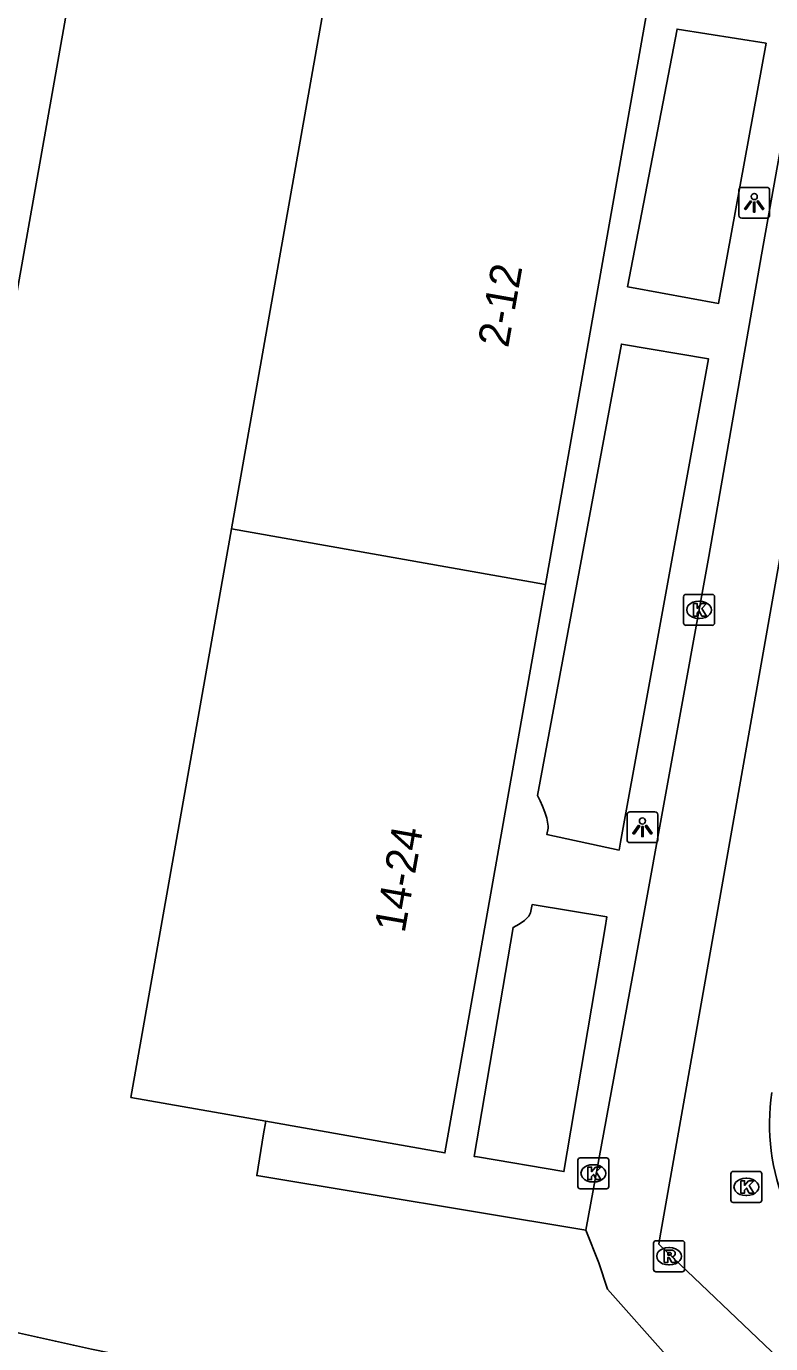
# Model space of a CAD drawing. Extents: x 161402 to 161933, y 381650 to 382313.
# Drawn here: x 161750.87 to 161774.94, y 381882.31 to 381924.89 of the extents above; entities that cross this region are included whole.
import ezdxf

# ---------------------------------------------------------------- set-up
doc = ezdxf.new("R2010")
doc.units = 0
for name, color, linetype in [('IMGEO_Groenvoorziening', 7, 'Continuous'), ('IMGEO_Kolk', 7, 'Continuous'), ('IMGEO_Lichtpunt', 7, 'Continuous'), ('IMGEO_Pand', 7, 'Continuous'), ('IMGEO_Pand_nummerreeks', 7, 'Continuous'), ('IMGEO_Parkeervlak_open', 7, 'Continuous'), ('IMGEO_Rijbaan_lokaal_open', 7, 'Continuous'), ('IMGEO_Rioolput', 7, 'Continuous'), ('IMGEO_Voetpad_gesloten', 7, 'Continuous'), ('IMGEO_Voetpad_open', 7, 'Continuous')]:
    doc.layers.add(name, color=color, linetype=linetype)

msp = doc.modelspace()

# ---------------------------------------------------------------- linework, layer by layer
at = {"layer": 'IMGEO_Groenvoorziening'}
msp.add_lwpolyline([(161761.561, 381932.294), (161753.635, 381933.615), (161746.013, 381890.587)], dxfattribs=at)
at = {"layer": 'IMGEO_Kolk'}
for p, q in [((161772.122, 381905.603), (161772.122, 381906.455)), ((161772.197, 381906.529), (161773.049, 381906.529)), ((161773.123, 381906.455), (161773.123, 381905.603)), ((161772.61, 381906.309), (161772.635, 381906.309)), ((161772.633, 381905.749), (161772.608, 381905.749)), ((161773.049, 381905.529), (161772.197, 381905.529)), ((161768.704, 381887.392), (161768.704, 381888.244)), ((161768.779, 381888.318), (161769.631, 381888.318)), ((161769.705, 381888.244), (161769.705, 381887.392)), ((161769.192, 381888.098), (161769.217, 381888.098)), ((161773.651, 381886.952), (161773.651, 381887.804)), ((161773.726, 381887.878), (161774.578, 381887.878)), ((161774.652, 381887.804), (161774.652, 381886.952)), ((161769.631, 381887.318), (161768.779, 381887.318)), ((161769.215, 381887.538), (161769.19, 381887.538)), ((161774.139, 381887.658), (161774.164, 381887.658)), ((161774.578, 381886.878), (161773.726, 381886.878)), ((161774.162, 381887.098), (161774.137, 381887.098))]:
    msp.add_line(p, q, dxfattribs=at)
for points in [[(161772.122, 381905.603), (161772.122, 381906.455)], [(161772.197, 381906.529), (161773.049, 381906.529)], [(161773.123, 381906.455), (161773.123, 381905.603)], [(161772.443, 381906.229), (161772.566, 381906.229), (161772.566, 381906.078), (161772.696, 381906.229), (161772.86, 381906.229), (161772.714, 381906.078), (161772.867, 381905.829), (161772.715, 381905.829), (161772.63, 381905.993), (161772.566, 381905.926), (161772.566, 381905.829), (161772.443, 381905.829), (161772.443, 381906.229)], [(161773.049, 381905.529), (161772.197, 381905.529)], [(161768.704, 381887.392), (161768.704, 381888.244)], [(161768.779, 381888.318), (161769.631, 381888.318)], [(161769.705, 381888.244), (161769.705, 381887.392)], [(161769.025, 381888.018), (161769.148, 381888.018), (161769.148, 381887.867), (161769.278, 381888.018), (161769.442, 381888.018), (161769.296, 381887.867), (161769.449, 381887.618), (161769.297, 381887.618), (161769.212, 381887.782), (161769.148, 381887.715), (161769.148, 381887.618), (161769.025, 381887.618), (161769.025, 381888.018)], [(161773.651, 381886.952), (161773.651, 381887.804)], [(161773.726, 381887.878), (161774.578, 381887.878)], [(161774.652, 381887.804), (161774.652, 381886.952)], [(161769.631, 381887.318), (161768.779, 381887.318)], [(161773.972, 381887.578), (161774.095, 381887.578), (161774.095, 381887.427), (161774.225, 381887.578), (161774.389, 381887.578), (161774.243, 381887.427), (161774.396, 381887.178), (161774.244, 381887.178), (161774.159, 381887.342), (161774.095, 381887.275), (161774.095, 381887.178), (161773.972, 381887.178), (161773.972, 381887.578)], [(161774.578, 381886.878), (161773.726, 381886.878)]]:
    msp.add_lwpolyline(points, dxfattribs=at)
for centre, start, end in [((161772.199, 381906.453), 91.552, 178.448), ((161772.199, 381906.453), 91.552, 178.448), ((161773.047, 381906.453), 1.552, 88.448), ((161773.047, 381906.453), 1.552, 88.448), ((161772.199, 381905.605), 181.552, 268.448), ((161772.199, 381905.605), 181.552, 268.448), ((161773.047, 381905.605), 271.552, 358.448), ((161773.047, 381905.605), 271.552, 358.448), ((161768.781, 381888.242), 91.552, 178.448), ((161768.781, 381888.242), 91.552, 178.448), ((161769.629, 381888.242), 1.552, 88.448), ((161769.629, 381888.242), 1.552, 88.448), ((161773.728, 381887.802), 91.552, 178.448), ((161773.728, 381887.802), 91.552, 178.448), ((161774.576, 381887.802), 1.552, 88.448), ((161774.576, 381887.802), 1.552, 88.448), ((161768.781, 381887.394), 181.552, 268.448), ((161768.781, 381887.394), 181.552, 268.448), ((161769.629, 381887.394), 271.552, 358.448), ((161769.629, 381887.394), 271.552, 358.448), ((161773.728, 381886.954), 181.552, 268.448), ((161773.728, 381886.954), 181.552, 268.448), ((161774.576, 381886.954), 271.552, 358.448), ((161774.576, 381886.954), 271.552, 358.448)]:
    msp.add_arc(centre, 0.0765, start, end, dxfattribs=at)
for centre, major_axis, ratio, start_param, end_param in [((161772.609, 381906.029), (-0.387, 0.002), 0.722429, 4.712389, 7.853982), ((161772.634, 381906.029), (-0.39, 0.002), 0.717154, 1.570796, 4.712389), ((161769.191, 381887.818), (-0.387, 0.002), 0.722429, 4.712389, 7.853982), ((161769.216, 381887.818), (-0.39, 0.002), 0.717154, 1.570796, 4.712389), ((161774.138, 381887.378), (-0.387, 0.002), 0.722429, 4.712389, 7.853982), ((161774.163, 381887.378), (-0.39, 0.002), 0.717154, 1.570796, 4.712389)]:
    msp.add_ellipse(centre, major_axis=major_axis, ratio=ratio, start_param=start_param, end_param=end_param, dxfattribs=at)
at = {"layer": 'IMGEO_Lichtpunt'}
for p, q in [((161774.809, 381919.684), (161774.001, 381919.684)), ((161774.809, 381919.684), (161774.001, 381919.684)), ((161773.907, 381919.589), (161773.907, 381918.782)), ((161773.907, 381919.589), (161773.907, 381918.782)), ((161774.903, 381918.782), (161774.903, 381919.589)), ((161774.903, 381918.782), (161774.903, 381919.589)), ((161774.001, 381918.688), (161774.809, 381918.688)), ((161774.001, 381918.688), (161774.809, 381918.688)), ((161770.294, 381899.407), (161770.294, 381898.6)), ((161770.294, 381899.407), (161770.294, 381898.6)), ((161771.196, 381899.502), (161770.388, 381899.502)), ((161771.196, 381899.502), (161770.388, 381899.502)), ((161771.29, 381898.6), (161771.29, 381899.407)), ((161771.29, 381898.6), (161771.29, 381899.407)), ((161770.388, 381898.506), (161771.196, 381898.506)), ((161770.388, 381898.506), (161771.196, 381898.506))]:
    msp.add_line(p, q, dxfattribs=at)
for points in [[(161774.281, 381919.253), (161774.32, 381919.225), (161774.132, 381918.963), (161774.094, 381918.99), (161774.281, 381919.253)], [(161774.493, 381919.225), (161774.531, 381919.252), (161774.718, 381918.99), (161774.679, 381918.962), (161774.493, 381919.225)], [(161774.383, 381919.205), (161774.43, 381919.205), (161774.43, 381918.883), (161774.383, 381918.883), (161774.383, 381919.205)], [(161770.668, 381899.071), (161770.707, 381899.043), (161770.519, 381898.781), (161770.481, 381898.808), (161770.668, 381899.071)], [(161770.77, 381899.023), (161770.817, 381899.023), (161770.817, 381898.701), (161770.77, 381898.701), (161770.77, 381899.023)], [(161770.88, 381899.043), (161770.918, 381899.07), (161771.105, 381898.808), (161771.066, 381898.78), (161770.88, 381899.043)]]:
    msp.add_lwpolyline(points, dxfattribs=at)
for centre in [(161774.406, 381919.387), (161770.793, 381899.205)]:
    msp.add_circle(centre, 0.0994, dxfattribs=at)
for centre, start, end in [((161774.001, 381919.589), 90, 180), ((161774.001, 381919.589), 90, 180), ((161774.809, 381919.589), 0, 90), ((161774.809, 381919.589), 0, 90), ((161774.001, 381918.782), 180, 270), ((161774.001, 381918.782), 180, 270), ((161774.809, 381918.782), 270, 0), ((161774.809, 381918.782), 270, 360), ((161770.388, 381899.407), 90, 180), ((161770.388, 381899.407), 90, 180), ((161771.196, 381899.407), 0, 90), ((161771.196, 381899.407), 0, 90), ((161770.388, 381898.6), 180, 270), ((161770.388, 381898.6), 180, 270), ((161771.196, 381898.6), 270, 0), ((161771.196, 381898.6), 270, 360)]:
    msp.add_arc(centre, 0.0946, start, end, dxfattribs=at)
at = {"layer": 'IMGEO_Pand'}
for points in [[(161757.508, 381908.649), (161760.759, 381927.025), (161770.911, 381925.228)], [(161770.911, 381925.228), (161767.659, 381906.853)], [(161758.611, 381889.504), (161754.257, 381890.274), (161757.508, 381908.649)], [(161767.659, 381906.853), (161757.508, 381908.649)], [(161767.659, 381906.853), (161764.408, 381888.478), (161758.611, 381889.504)]]:
    msp.add_lwpolyline(points, dxfattribs=at)
at = {"layer": 'IMGEO_Parkeervlak_open'}
msp.add_lwpolyline([(161768.961, 381885.978), (161769.381, 381884.923), (161769.662, 381884.07), (161771.638, 381881.858), (161773.952, 381879.809), (161774.308, 381879.519)], dxfattribs=at)
at = {"layer": 'IMGEO_Rijbaan_lokaal_open'}
msp.add_lwpolyline([(161775.809, 381923.999), (161778.071, 381923.6), (161776.189, 381913.114), (161771.355, 381885.738), (161771.319, 381885.533), (161786.796, 381870.79)], dxfattribs=at)
msp.add_arc((161781.898, 381889.424), 6.999, 171.766, 202.7426, dxfattribs=at)
at = {"layer": 'IMGEO_Rioolput'}
for p, q in [((161771.228, 381885.639), (161772.08, 381885.639)), ((161771.153, 381884.713), (161771.153, 381885.565)), ((161771.641, 381885.419), (161771.666, 381885.419)), ((161772.154, 381885.565), (161772.154, 381884.713)), ((161771.664, 381884.859), (161771.639, 381884.859)), ((161772.08, 381884.639), (161771.228, 381884.639))]:
    msp.add_line(p, q, dxfattribs=at)
for points in [[(161771.228, 381885.639), (161772.08, 381885.639)], [(161771.153, 381884.713), (161771.153, 381885.565)], [(161771.742, 381885.337), (161771.49, 381885.339), (161771.49, 381884.939)], [(161771.668, 381885.258), (161771.614, 381885.258), (161771.614, 381885.177)], [(161771.614, 381885.177), (161771.666, 381885.177)], [(161772.154, 381885.565), (161772.154, 381884.713)], [(161771.49, 381884.939), (161771.614, 381884.939), (161771.614, 381885.101), (161771.625, 381885.101)], [(161771.672, 381885.072), (161771.743, 381884.939), (161771.883, 381884.939), (161771.818, 381885.065)], [(161772.08, 381884.639), (161771.228, 381884.639)]]:
    msp.add_lwpolyline(points, dxfattribs=at)
for centre, radius, start, end in [((161771.23, 381885.563), 0.0765, 91.552, 178.448), ((161771.23, 381885.563), 0.0765, 91.552, 178.448), ((161772.078, 381885.563), 0.0765, 1.552, 88.448), ((161772.078, 381885.563), 0.0765, 1.552, 88.448), ((161771.65, 381885.366), 0.19, 274.7715, 282.9687), ((161771.674, 381885.162), 0.0964, 77.0061, 93.1865), ((161771.688, 381885.219), 0.0378, 276.6634, 79.6772), ((161771.741, 381885.227), 0.109, 350.3612, 89.416), ((161771.739, 381885.227), 0.112, 277.5842, 350.9817), ((161771.624, 381885.048), 0.0533, 26.0293, 88.6989), ((161771.723, 381885.012), 0.108, 29.5134, 73.7905), ((161771.23, 381884.715), 0.0765, 181.552, 268.448), ((161771.23, 381884.715), 0.0765, 181.552, 268.448), ((161772.078, 381884.715), 0.0765, 271.552, 358.448), ((161772.078, 381884.715), 0.0765, 271.552, 358.448)]:
    msp.add_arc(centre, radius, start, end, dxfattribs=at)
for centre, major_axis, ratio, start_param, end_param in [((161771.64, 381885.139), (-0.387, 0.002), 0.722429, 4.712389, 7.853982), ((161771.665, 381885.139), (-0.39, 0.002), 0.717154, 1.570796, 4.712389)]:
    msp.add_ellipse(centre, major_axis=major_axis, ratio=ratio, start_param=start_param, end_param=end_param, dxfattribs=at)
at = {"layer": 'IMGEO_Voetpad_gesloten'}
msp.add_arc((161773.213, 381979.731), 99.666, 253.48297, 264.46507, dxfattribs=at)
at = {"layer": 'IMGEO_Voetpad_open'}
for points in [[(161770.307, 381916.473), (161771.914, 381924.8), (161774.788, 381924.343), (161773.256, 381915.934), (161770.437, 381916.449), (161770.307, 381916.473)], [(161775.809, 381923.999), (161774.646, 381917.502), (161772.935, 381907.756), (161770.541, 381894.588), (161768.961, 381885.978)], [(161767.404, 381900.027), (161770.112, 381914.616), (161772.929, 381914.138), (161770.086, 381898.523), (161770.039, 381898.265), (161767.706, 381898.766), (161767.745, 381898.97)], [(161767.635, 381899.489), (161767.556, 381899.683), (161767.48, 381899.856), (161767.404, 381900.027)], [(161767.228, 381896.511), (161769.643, 381896.103), (161769.585, 381895.761), (161768.253, 381887.875), (161765.464, 381888.346), (161765.347, 381888.366), (161766.609, 381895.764), (161766.803, 381895.872), (161766.978, 381895.991), (161767.115, 381896.132), (161767.174, 381896.24), (161767.228, 381896.511)], [(161758.611, 381889.504), (161758.545, 381889.099), (161758.322, 381887.744), (161768.961, 381885.978)]]:
    msp.add_lwpolyline(points, dxfattribs=at)
msp.add_arc((161766.287, 381898.932), 1.458, 1.4862, 22.4469, dxfattribs=at)

# ---------------------------------------------------------------- texts
at = {"layer": 'IMGEO_Pand_nummerreeks'}
for s, p in [('2-12', (161766.449, 381914.474)), ('14-24', (161763.101, 381895.559))]:
    msp.add_text(s, height=1, rotation=79.9653, dxfattribs=at).set_placement(p)

doc.saveas('drawing.dxf')
